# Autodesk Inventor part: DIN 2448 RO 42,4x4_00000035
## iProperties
Created: 2006-02
Part Number: DIN 2448 RO 42,4x4_00000035
Material: Default
Document SubType Name: Modeling
Designer: FranzK
Stock Number: DIN 2448 RO 42,4x4
Mass: 151.597 g
Surface Area: 767.637 cm^2
Volume: 151.597 cm^3
Density: 1 g/cm^3
G_L: 314.159 mm
G_W: 42.400 mm
G_H: 42.400 mm
AFG_Item: 42.4 x 4
CSToolsMass: 0.2
CSToolsVolume: 151597.0
CSToolsArea: 768.0
Author: FranzK
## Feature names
1. AFG_Detailed_DIN 2448 RO 42,4x4_00000035
2. AFG_Simplified_DIN 2448 RO 42,4x4_00000035
